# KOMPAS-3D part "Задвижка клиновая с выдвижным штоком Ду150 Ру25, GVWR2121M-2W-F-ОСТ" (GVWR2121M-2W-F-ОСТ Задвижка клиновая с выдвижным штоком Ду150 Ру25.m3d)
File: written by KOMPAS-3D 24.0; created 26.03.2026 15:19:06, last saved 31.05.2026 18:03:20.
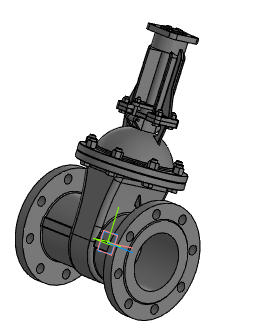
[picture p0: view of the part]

Document properties: Автор: R2D2; Полное имя файла: E:\Работа\Зайцев\GVWR2121M-2W-F-ОСТ Задвижка клиновая 30с964нж DN.ru Ду50-300 Ру25\исходные материалы\DN150\DN150\GVWR2121M-2W-F-ОСТ Задвижка клиновая с выдвижным штоком Ду150 Ру25.m3d

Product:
- Part/product: Задвижка клиновая с выдвижным штоком Ду150 Ру25  | designation GVWR2121M-2W-F-ОСТ
    Масса: 60
    Раздел спецификации: Прочие изделия
    Примечание: D040-08602
    additional columns: D040-10013

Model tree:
1. Операция без истории:1

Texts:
  GVWR2121M-2W-F-ОСТ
